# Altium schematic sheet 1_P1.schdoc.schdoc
size 309 x 223 mm; Symbol: Sheet-Symbol_A4; Device: Sheet-Symbol_A4; Company: 嘉立创EDA; Version: V1.0; Page Size: A4; @Project Name: 20240125_无人机探照灯_6; @Page Count: 1; @Update Date: 2024-03-25; @Create Date: 2024-01-31; @Schematic Name: schematic1; @Page No: 1; @Page Name: P1
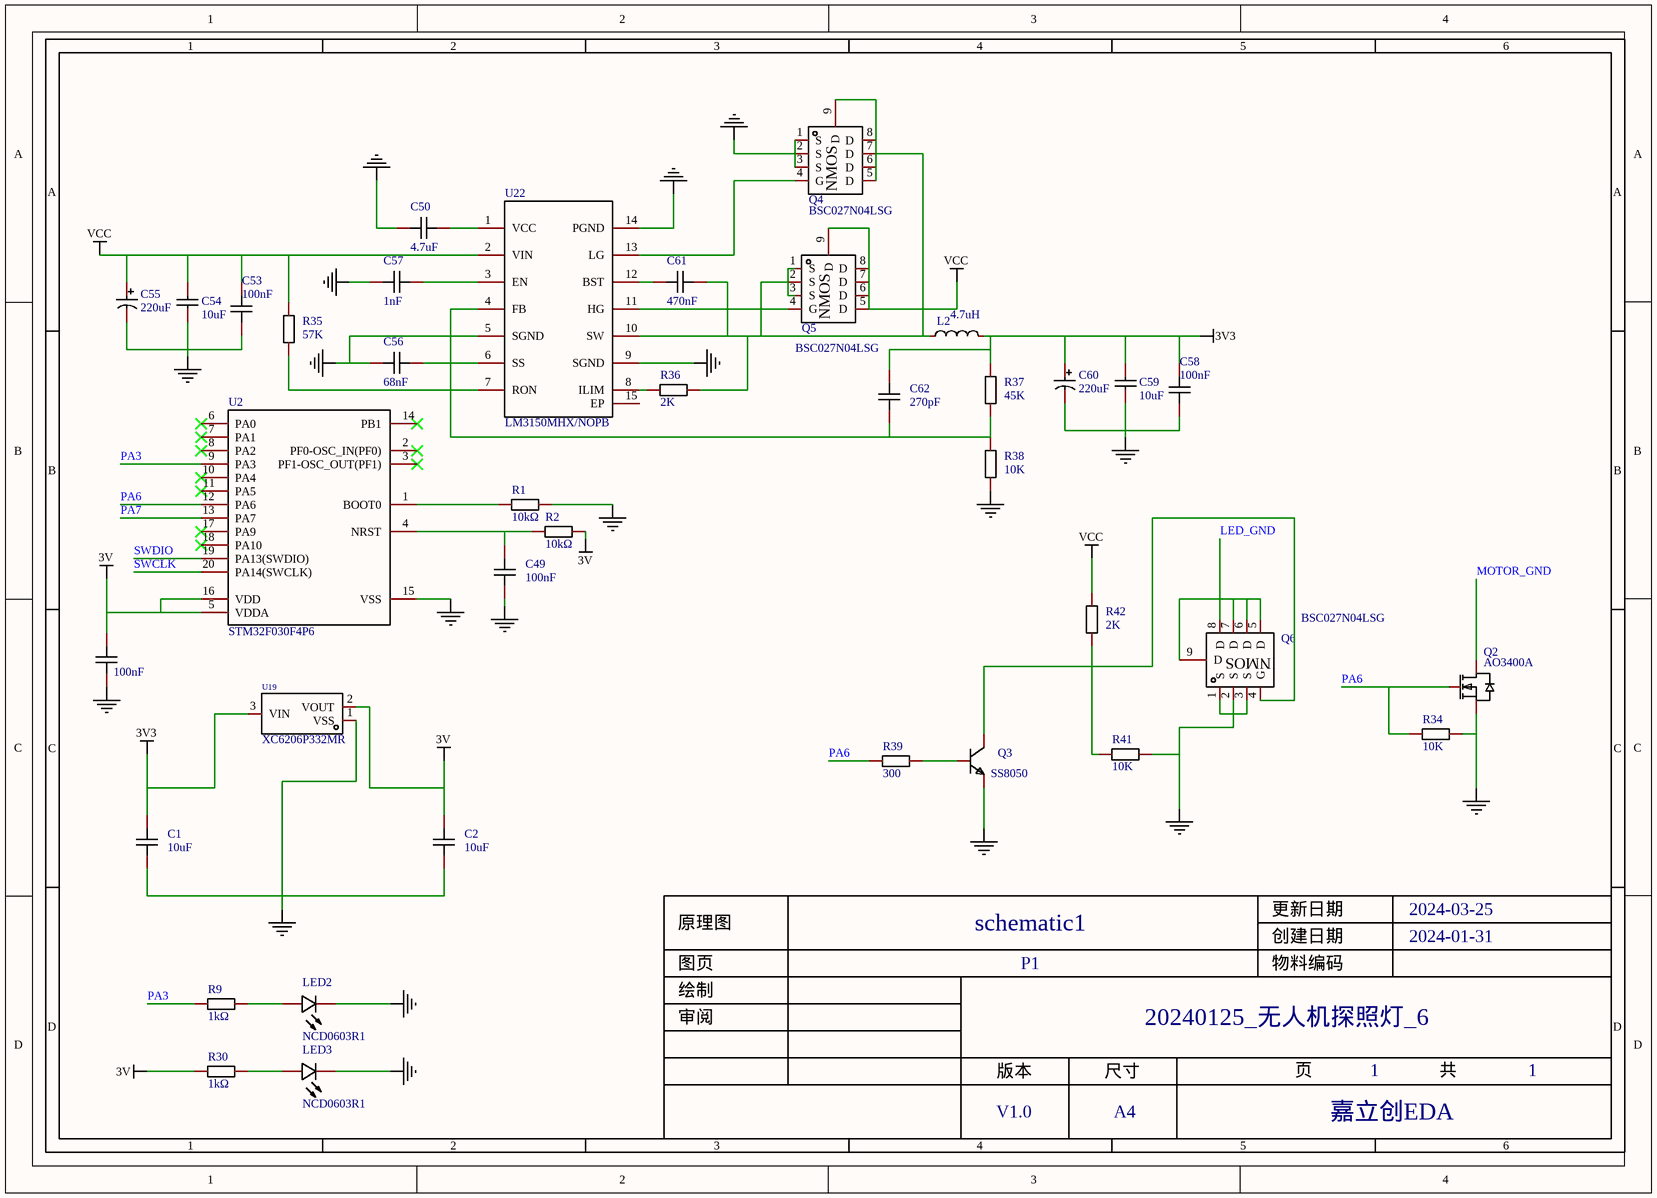
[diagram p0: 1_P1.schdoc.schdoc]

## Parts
C1  10uF  [C0603]
C2  10uF  [C0603]
C16  100nF  [C0603]
C49  100nF  [C0603]
C50  4.7uF  [C0603]
C53  100nF  [C0603]
C54  10uF  [C1206]
C55  220uF  [CAP-TH_BD8.0-P3.50-D0.6-FD]
C56  68nF  [C0603]
C57  1nF  [C0603]
C58  100nF  [C0603]
C59  10uF  [C1206]
C60  220uF  [CAP-TH_BD8.0-P3.50-D0.6-FD]
C61  470nF  [C0603]
C62  270pF  [C0603]
L2  4.7uH  [IND-SMD_L7.3-W6.6]
LED2  NCD0603R1  [LED0603-RD_RED]
LED3  NCD0603R1  [LED0603-RD_RED]
Q2  AO3400A  [SOT-23-3_L2.9-W1.3-P1.90-LS2.4-BR]
Q3  SS8050  [SOT-23-3_L2.9-W1.3-P1.90-LS2.4-BR]
Q4  BSC027N04LSG  [PG-TDSON-8_L5.0-W6.0-P1.27-LS6.2-BL-EP]
Q5  BSC027N04LSG  [PG-TDSON-8_L5.0-W6.0-P1.27-LS6.2-BL-EP]
Q6  BSC027N04LSG  [PG-TDSON-8_L5.0-W6.0-P1.27-LS6.2-BL-EP]
R1  10kΩ  [R0603]
R2  10kΩ  [R0603]
R9  1kΩ  [R0603]
R30  1kΩ  [R0603]
R34  10K  [R0603]
R35  57K  [R0603]
R36  2K  [R0603]
R37  45K  [R0603]
R38  10K  [R0603]
R39  300  [R0603]
R41  10K  [R0603]
R42  2K  [R0603]
U2  STM32F030F4P6  [TSSOP-20_L6.5-W4.4-P0.65-LS6.4-BL]
U19  XC6206P332MR  [SOT-23-3_L3.0-W1.7-P0.95-LS2.9-BR]
U22  LM3150MHX/NOPB  [HTSSOP-14_L5.0-W4.4-P0.65-LS6.4-BL-EP]

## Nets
3V: C2.2 C16.2 R2.2 R30.2 U2.5(VDDA) U2.16(VDD) U19.2(VOUT)
3V3: C1.2 C58.2 C59.2 C60.1 C62.1 L2.2 R37.2 U19.3(VIN)
NetC1_1: C1.1 C2.1 C16.1 C49.1 C50.1 C53.1 C54.1 C55.2 C56.1 C57.1 C58.1 C59.1 C60.2 LED2.1(K) LED3.1(K) Q2.2(S) Q3.2(E) Q4.1(S) Q4.2(S) Q4.3(S) Q6.1(S) Q6.2(S) Q6.3(S) R1.2 R34.2 R38.1 R41.2 U2.15(VSS) U19.1(VSS) U22.5(SGND) U22.9(SGND) U22.14(PGND)
VCC: C53.2 C54.2 C55.1 Q5.5(D) Q5.6(D) Q5.7(D) Q5.8(D) Q5.9(D) R35.2 R42.2 U22.2(VIN)
LED_GND: Q6.5(D) Q6.6(D) Q6.7(D) Q6.8(D) Q6.9(D)
MOTOR_GND: Q2.3(D)
PA3: R9.2 U2.9(PA3)
PA6: Q2.1(G) R34.1 R39.1 U2.12(PA6)
PA7: U2.13(PA7)
SWCLK: U2.20(PA14(SWCLK))
SWDIO: U2.19(PA13(SWDIO))
NetC49_2: C49.2 R2.1 U2.4(NRST)
NetC50_2: C50.2 U22.1(VCC)
NetC56_2: C56.2 U22.6(SS)
NetC57_2: C57.2 U22.3(EN)
NetC61_1: C61.1 U22.12(BST)
NetC61_2: C61.2 L2.1 Q4.5(D) Q4.6(D) Q4.7(D) Q4.8(D) Q4.9(D) Q5.1(S) Q5.2(S) Q5.3(S) R36.2 U22.10(SW)
NetC62_2: C62.2 R37.1 R38.2 U22.4(FB)
NetLED2_2: LED2.2(A) R9.1
NetLED3_2: LED3.2(A) R30.1
NetQ3_1: Q3.1(B) R39.2
NetQ3_3: Q3.3(C) Q6.4(G) R41.1 R42.1
NetQ4_4: Q4.4(G) U22.13(LG)
NetQ5_4: Q5.4(G) U22.11(HG)
NetR1_1: R1.1 U2.1(BOOT0)
NetR35_1: R35.1 U22.7(RON)
NetR36_1: R36.1 U22.8(ILIM)

Not connected (* = marked no-connect by the designer): U2 2(PF0-OSC_IN(PF0))* 3(PF1-OSC_OUT(PF1))* 6(PA0)* 7(PA1)* 8(PA2)* 10(PA4)* 11(PA5)* 14(PB1)* 17(PA9)* 18(PA10)*; U22 15(EP)

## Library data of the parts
C1 C2 C16 = CL10A106KP8NNNC: Manufacturer: SAMSUNG(三星); Add into BOM: yes; Tolerance: ±10%; Voltage Rated: 10V; Temperature Coefficient: X5R; Description: 容值:10uF;精度:±10%;额定电压:10V;材质(温度系数):X5R;
C49 C50 C53 C56-C58 C61 C62 = CAP_0603: Symbol: CapAcitance; Convert to PCB: yes
C54 C59 = CL31A106KBHNNNE: Manufacturer: SAMSUNG(三星); Add into BOM: yes; Tolerance: ±10%; Voltage Rated: 50V; Temperature Coefficient: X5R; Description: 容值:10uF;精度:±10%;额定电压:50V;材质(温度系数):X5R;
C55 C60 = KM227M035F12RR0VH2FP0: Manufacturer: CX(承兴); Symbol: 220uf/35V; Add into BOM: yes; Tolerance: ±20%; Rated Voltage: 35V; φD: 8mm; L: 12mm; Lifetime @ Temp: 2000hrs@105℃; Description: 容值:220uF;精度:±20%;额定电压:35V;纹波电流:-;等效串联电阻:-;
L2 = MCS0630-100MPY1: Manufacturer: PSA(信昌电陶); Add into BOM: yes; Tolerance: ±20%; Rated Current: 4A; Saturation Current (Isat): 5.5A; DC Resistance (DCR): 62mΩ; Description: 电感值:10uH;精度:±20%;额定电流:4A;饱和电流(Isat):5.5A;
LED2 LED3 = NCD0603R1_C84263: Manufacturer: 国星光电; Symbol: FC-DA1608HRK-620D; Add into BOM: yes; Emitted Color: 红灯; Description: 发光颜色:红灯;
Q2 = AO3400A_C347475: Manufacturer: UMW(友台半导体); Add into BOM: yes; Type: N沟道; Drain Source Voltage (Vdss): 30V; Continuous Drain Current (Id): 5.8A; Power Dissipation (Pd): 1.4W; Drain Source On Resistance (RDS(on)@Vgs,Id): 35mΩ@10V,5.8A; Gate Threshold Voltage (Vgs(th)@Id): 1.4V@250uA; Total Gate Charge (Qg@Vgs): 12nC@4.5V; Input Capacitance (Ciss@Vds): 1.05nF@15V; Description: 类型:N沟道;漏源电压(Vdss):30V;连续漏极电流(Id):5.8A;功率(Pd):1.4W;导通电阻(RDS(on)@Vgs,Id):35mΩ@10V,5.8A;阈值电压(Vgs(th)@Id):1.4V@250uA;
Q3 = SS8050_C2150: Manufacturer: CJ(江苏长电/长晶); Add into BOM: yes; Transistor Type: NPN; Collector Current (Ic): 1.5A; Collector-Emitter Breakdown Voltage (Vceo): 25V; Power Dissipation (Pd): 300mW; DC Current Gain (hFE@Ic,Vce): 200@100mA,1V; Transition Frequency (fT): 100MHz; Collector Cut-Off Current (Icbo): 100nA; Collector-Emitter Saturation Voltage (VCE(sat)@Ic,Ib): 500mV@800mA,80mA; Description: 晶体管类型:NPN;集电极电流(Ic):1.5A;集射极击穿电压(Vceo):25V;功率(Pd):300mW;直流电流增益(hFE@Ic,Vce):200@100mA,1V;
Q4-Q6 = BSC027N04LSG: Manufacturer: Infineon(英飞凌); Add into BOM: yes; Description: 类型:-;漏源电压(Vdss):-;连续漏极电流(Id):-;功率(Pd):-;导通电阻(RDS(on)@Vgs,Id):-;阈值电压(Vgs(th)@Id):-;
R1 R2 = 0603WAF1002T5E: Manufacturer: UNI-ROYAL(厚声); Add into BOM: yes; Tolerance: ±1%; Power(Watts): 100mW; Temperature Coefficient: ±100ppm/℃; Overload Voltage (Max): 75V; Description: 电阻类型:厚膜电阻;阻值:10kΩ;精度:±1%;功率:100mW;
R9 R30 = 0603WAF1001T5E: Manufacturer: UNI-ROYAL(厚声); Add into BOM: yes; Tolerance: ±1%; Power(Watts): 100mW; Temperature Coefficient: ±100ppm/℃; Overload Voltage (Max): 75V; Description: 电阻类型:厚膜电阻;阻值:1kΩ;精度:±1%;功率:100mW;
R34-R39 R41 R42 = Res_0603: Symbol: 电阻; Convert to PCB: yes
U2 = STM32F030F4P6: Manufacturer: ST(意法半导体); Add into BOM: yes; CPU Core: ARM Cortex-M0; CPU Maximum Speed: 48MHz; Operating Voltage Range: 2.4V~3.6V; Program Storage Size: 16KB; Program Memory Type: FLASH; RAM Size: 4KB; GPIO Ports Number: 15; ADC (Bit): 12bit; Watchdog: 有; Description: CPU内核:ARM Cortex-M0;CPU最大主频:48MHz;程序存储容量:16KB;程序存储器类型:FLASH;RAM总容量:4KB;GPIO端口数量:15;
U19 = XC6206P332MR_C347376: Manufacturer: UMW(友台半导体); Add into BOM: yes; Output Type: 固定; Output Polarity: 正; Number of Outputs: 1; Maximum Input Voltage: 8V; Output Voltage: 3.3V; Dropout Voltage: 240mV@(50mA); Output Current: 250mA; Power Supply Rejection Ratio (PSRR): 40dB@(1kHz); Description: 输出类型:固定;输出极性:正;最大输入电压:8V;输出电压:3.3V;输出电流:250mA;电源纹波抑制比(PSRR):40dB@(1kHz);
U22 = LM3150MHX/NOPB: Manufacturer: TI(德州仪器); Add into BOM: yes; Function: 降压型; Input Voltage: 6V~42V; Output Current (Max): 12A; Switching Frequency: 1MHz; Synchronous Rectification: 是; Number of Outputs: 1; Topology: 降压式; Description: 功能类型:降压型;输入电压:6V~42V;输出电流(最大值):12A;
